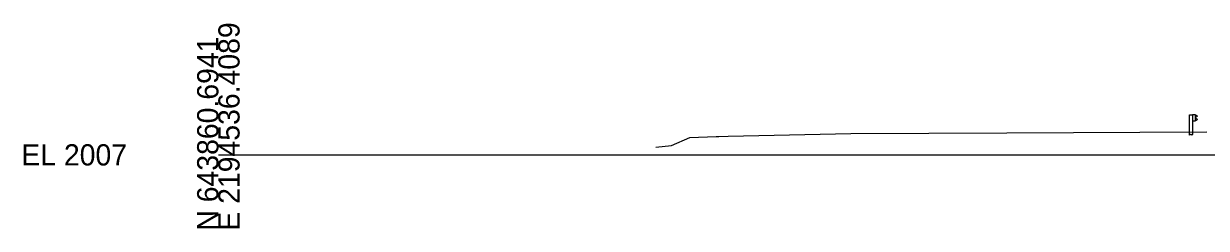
# Model space of a CAD drawing. Extents: x -26 to 303, y -10 to 11030.
# Drawn here: x -25.7 to 130.4, y 6990.3 to 7017.3 of the extents above; entities that cross this region are included whole.
import ezdxf

# ---------------------------------------------------------------- set-up
doc = ezdxf.new("R2010")
doc.units = 0
for name, color, linetype in [('DESIGN - SHEET - Light Grid', 7, 'Continuous'), ('DESIGN - TYPICAL - Finished Grade and Subgrade', 7, 'Continuous'), ('DESIGN - TYPICAL - Guardrail', 7, 'Continuous'), ('SURVEY - GROUND - Top of Ground', 7, 'Continuous')]:
    doc.layers.add(name, color=color, linetype=linetype)

msp = doc.modelspace()

# ---------------------------------------------------------------- linework, layer by layer
at = {"layer": 'DESIGN - SHEET - Light Grid'}
msp.add_line((0, 7000), (150, 7000), dxfattribs=at)
at = {"layer": 'DESIGN - TYPICAL - Finished Grade and Subgrade'}
msp.add_line((130.37, 7002.93), (130.37, 7003.04), dxfattribs=at)
at = {"layer": 'DESIGN - TYPICAL - Guardrail'}
for p, q in [((128.16, 7004.49), (128.16, 7004.49)), ((128.16, 7004.49), (128.16, 7004.49)), ((128.56, 7004.49), (128.56, 7004.49)), ((128.56, 7004.49), (128.56, 7004.49)), ((128.26, 7002.67), (128.16, 7002.59)), ((128.44, 7002.65), (128.35, 7002.68)), ((128.56, 7002.69), (128.51, 7002.66))]:
    msp.add_line(p, q, dxfattribs=at)
for points in [[(128.16, 7002.59), (128.16, 7005.28), (128.56, 7005.28), (128.56, 7002.69)], [(128.56, 7004.5), (128.96, 7004.5), (128.96, 7005.28), (128.56, 7005.28)], [(128.96, 7005.25), (129.03, 7005.24), (129.17, 7005.14), (129.19, 7005.11), (129.17, 7005.08), (128.98, 7004.96), (128.96, 7004.93), (128.96, 7004.85), (128.98, 7004.82), (129.17, 7004.7), (129.19, 7004.67), (129.17, 7004.64), (129.03, 7004.54), (128.96, 7004.53)]]:
    msp.add_lwpolyline(points, dxfattribs=at)
for centre, start, end in [((128.32, 7002.58), 74.0986, 124.6952), ((128.46, 7002.75), 254.0986, 298.996)]:
    msp.add_arc(centre, 0.1, start, end, dxfattribs=at)
at = {"layer": 'SURVEY - GROUND - Top of Ground'}
msp.add_lwpolyline([(57.72, 7001), (59.78, 7001.22), (62.23, 7002.31), (65.68, 7002.43), (66.03, 7002.44), (67.26, 7002.46), (83.44, 7002.8), (104.05, 7002.92), (130.37, 7003.04)], dxfattribs=at)

# ---------------------------------------------------------------- texts
at = {"layer": 'DESIGN - SHEET - Light Grid'}
for s, p in [('E 2194536.4089', (2.8, 6990)), ('N 643860.6941', (0, 6990))]:
    msp.add_text(s, height=2.8, rotation=90, dxfattribs=at).set_placement(p)
msp.add_text('EL 2007', height=2.8, dxfattribs=at).set_placement((-26, 6998.6))

doc.saveas('drawing.dxf')
